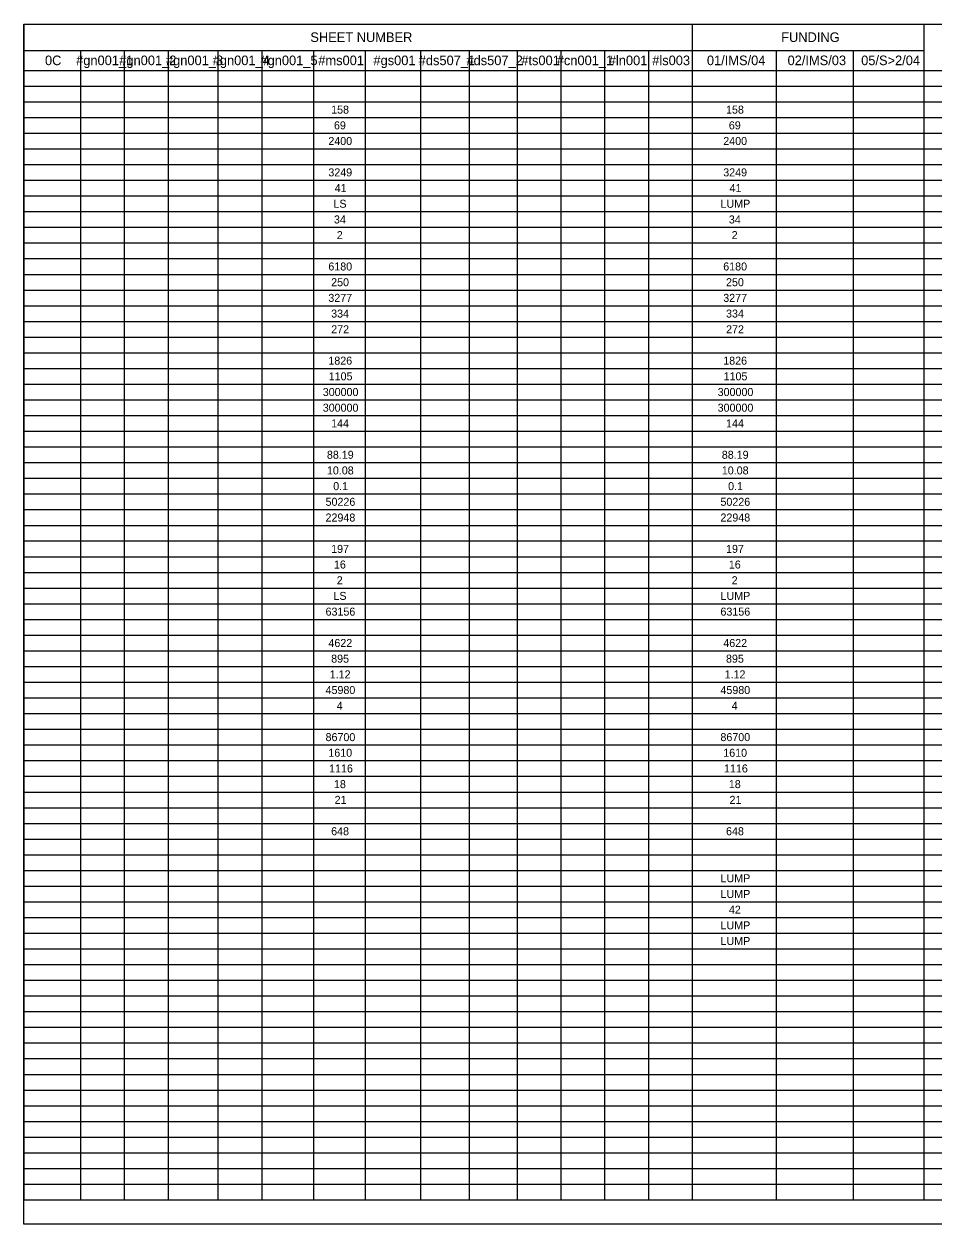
# Model space of a CAD drawing. Extents: x -542 to 295, y -281 to 32.
# Drawn here: x -416.36 to -400.45, y -160.59 to -139.59 of the extents above; entities that cross this region are included whole.
import ezdxf

# ---------------------------------------------------------------- set-up
doc = ezdxf.new("R2010")
doc.units = 0
for name, color, linetype in [('SC_Scratch1', 7, 'Continuous'), ('SH_Data', 7, 'Continuous'), ('SH_Text', 7, 'Continuous')]:
    doc.layers.add(name, color=color, linetype=linetype)

msp = doc.modelspace()

# ---------------------------------------------------------------- linework, layer by layer
at = {"layer": 'SC_Scratch1'}
msp.add_lwpolyline([(-416.359, -139.593), (-385.859, -139.593), (-385.859, -160.593), (-416.359, -160.593)], close=True, dxfattribs=at)
at = {"layer": 'SH_Data'}
for p, q in [((-416.359, -139.593), (-385.859, -139.593)), ((-416.359, -139.593), (-416.359, -160.17)), ((-404.663, -139.593), (-404.663, -160.17)), ((-400.608, -139.593), (-400.608, -160.17)), ((-416.359, -140.054), (-400.608, -140.054)), ((-415.369, -140.054), (-415.369, -160.17)), ((-414.603, -140.054), (-414.603, -160.17)), ((-413.836, -140.054), (-413.836, -160.17)), ((-412.964, -140.054), (-412.964, -160.17)), ((-412.198, -140.054), (-412.198, -160.17)), ((-411.293, -140.054), (-411.293, -160.17)), ((-410.388, -140.054), (-410.388, -160.17)), ((-409.42, -140.054), (-409.42, -160.17)), ((-408.569, -140.054), (-408.569, -160.17)), ((-407.728, -140.054), (-407.728, -160.17)), ((-406.962, -140.054), (-406.962, -160.17)), ((-406.195, -140.054), (-406.195, -160.17)), ((-405.429, -140.054), (-405.429, -160.17)), ((-403.194, -140.054), (-403.194, -160.17)), ((-401.843, -140.054), (-401.843, -160.17)), ((-416.359, -140.405), (-385.859, -140.405)), ((-416.359, -140.68), (-385.859, -140.68)), ((-416.359, -140.954), (-385.859, -140.954)), ((-416.359, -141.229), (-385.859, -141.229)), ((-416.359, -141.503), (-385.859, -141.503)), ((-416.359, -141.778), (-385.859, -141.778)), ((-416.359, -142.052), (-385.859, -142.052)), ((-416.359, -142.327), (-385.859, -142.327)), ((-416.359, -142.601), (-385.859, -142.601)), ((-416.359, -142.876), (-385.859, -142.876)), ((-416.359, -143.15), (-385.859, -143.15)), ((-416.359, -143.425), (-385.859, -143.425)), ((-416.359, -143.699), (-385.859, -143.699)), ((-416.359, -143.974), (-385.859, -143.974)), ((-416.359, -144.248), (-385.859, -144.248)), ((-416.359, -144.523), (-385.859, -144.523)), ((-416.359, -144.797), (-385.859, -144.797)), ((-416.359, -145.072), (-385.859, -145.072)), ((-416.359, -145.346), (-385.859, -145.346)), ((-416.359, -145.621), (-385.859, -145.621)), ((-416.359, -145.895), (-385.859, -145.895)), ((-416.359, -146.17), (-385.859, -146.17)), ((-416.359, -146.444), (-385.859, -146.444)), ((-416.359, -146.719), (-385.859, -146.719)), ((-416.359, -146.993), (-385.859, -146.993)), ((-416.359, -147.268), (-385.859, -147.268)), ((-416.359, -147.542), (-385.859, -147.542)), ((-416.359, -147.817), (-385.859, -147.817)), ((-416.359, -148.091), (-385.859, -148.091)), ((-416.359, -148.366), (-385.859, -148.366)), ((-416.359, -148.64), (-385.859, -148.64)), ((-416.359, -148.915), (-385.859, -148.915)), ((-416.359, -149.189), (-385.859, -149.189)), ((-416.359, -149.464), (-385.859, -149.464)), ((-416.359, -149.738), (-385.859, -149.738)), ((-416.359, -150.013), (-385.859, -150.013)), ((-416.359, -150.287), (-385.859, -150.287)), ((-416.359, -150.562), (-385.859, -150.562)), ((-416.359, -150.836), (-385.859, -150.836)), ((-416.359, -151.111), (-385.859, -151.111)), ((-416.359, -151.385), (-385.859, -151.385)), ((-416.359, -151.66), (-385.859, -151.66)), ((-416.359, -151.935), (-385.859, -151.935)), ((-416.359, -152.209), (-385.859, -152.209)), ((-416.359, -152.484), (-385.859, -152.484)), ((-416.359, -152.758), (-385.859, -152.758)), ((-416.359, -153.033), (-385.859, -153.033)), ((-416.359, -153.307), (-385.859, -153.307)), ((-416.359, -153.582), (-385.859, -153.582)), ((-416.359, -153.856), (-385.859, -153.856)), ((-416.359, -154.131), (-385.859, -154.131)), ((-416.359, -154.405), (-385.859, -154.405)), ((-416.359, -154.68), (-385.859, -154.68)), ((-416.359, -154.68), (-385.859, -154.68)), ((-416.359, -154.954), (-385.859, -154.954)), ((-416.359, -155.229), (-385.859, -155.229)), ((-416.359, -155.503), (-385.859, -155.503)), ((-416.359, -155.778), (-385.859, -155.778)), ((-416.359, -156.052), (-385.859, -156.052)), ((-416.359, -156.327), (-385.859, -156.327)), ((-416.359, -156.601), (-385.859, -156.601)), ((-416.359, -156.876), (-385.859, -156.876)), ((-416.359, -157.15), (-385.859, -157.15)), ((-416.359, -157.425), (-385.859, -157.425)), ((-416.359, -157.699), (-385.859, -157.699)), ((-416.359, -157.974), (-385.859, -157.974)), ((-416.359, -158.248), (-385.859, -158.248)), ((-416.359, -158.523), (-385.859, -158.523)), ((-416.359, -158.797), (-385.859, -158.797)), ((-416.359, -159.072), (-385.859, -159.072)), ((-416.359, -159.346), (-385.859, -159.346)), ((-416.359, -159.621), (-385.859, -159.621)), ((-416.359, -159.895), (-385.859, -159.895)), ((-416.359, -160.17), (-385.859, -160.17))]:
    msp.add_line(p, q, dxfattribs=at)

# ---------------------------------------------------------------- texts
at = {"layer": 'SH_Text'}
for s, height, p in [('SHEET NUMBER', 0.168, (-411.346, -139.907)), ('FUNDING', 0.168, (-403.105, -139.907)), ('0C', 0.168, (-415.991, -140.313)), ('#gn001_1', 0.168, (-415.446, -140.313)), ('#gn001_2', 0.168, (-414.691, -140.313)), ('#gn001_3', 0.168, (-413.873, -140.313)), ('#gn001_4', 0.168, (-413.055, -140.313)), ('#gn001_5', 0.168, (-412.219, -140.313)), ('#ms001', 0.168, (-411.207, -140.313)), ('#gs001', 0.168, (-410.242, -140.313)), ('#ds507_1', 0.168, (-409.449, -140.313)), ('#ds507_2', 0.168, (-408.614, -140.313)), ('#ts001', 0.168, (-407.654, -140.313)), ('#cn001_1', 0.168, (-407.033, -140.313)), ('#ln001', 0.168, (-406.122, -140.313)), ('#ls003', 0.168, (-405.362, -140.313)), ('01/IMS/04', 0.168, (-404.405, -140.313)), ('02/IMS/03', 0.168, (-402.993, -140.313)), ('05/S>2/04', 0.168, (-401.705, -140.313)), ('158', 0.14, (-410.982, -141.161)), ('158', 0.14, (-404.07, -141.161)), ('69', 0.14, (-410.933, -141.436)), ('69', 0.14, (-404.021, -141.436)), ('2400', 0.14, (-411.031, -141.71)), ('2400', 0.14, (-404.119, -141.71)), ('3249', 0.14, (-411.031, -142.259)), ('3249', 0.14, (-404.119, -142.259)), ('41', 0.14, (-410.921, -142.534)), ('41', 0.14, (-404.009, -142.534)), ('LS', 0.14, (-410.942, -142.808)), ('LUMP', 0.14, (-404.166, -142.808)), ('34', 0.14, (-410.933, -143.083)), ('34', 0.14, (-404.021, -143.083)), ('2', 0.14, (-410.884, -143.357)), ('2', 0.14, (-403.972, -143.357)), ('6180', 0.14, (-411.031, -143.906)), ('6180', 0.14, (-404.119, -143.906)), ('250', 0.14, (-410.982, -144.181)), ('250', 0.14, (-404.07, -144.181)), ('3277', 0.14, (-411.031, -144.455)), ('3277', 0.14, (-404.119, -144.455)), ('334', 0.14, (-410.982, -144.73)), ('334', 0.14, (-404.07, -144.73)), ('272', 0.14, (-410.981, -145.005)), ('272', 0.14, (-404.069, -145.005)), ('1826', 0.14, (-411.031, -145.554)), ('1826', 0.14, (-404.119, -145.554)), ('1105', 0.14, (-411.025, -145.828)), ('1105', 0.14, (-404.113, -145.828)), ('300000', 0.14, (-411.129, -146.103)), ('300000', 0.14, (-404.217, -146.103)), ('300000', 0.14, (-411.129, -146.377)), ('300000', 0.14, (-404.217, -146.377)), ('144', 0.14, (-410.982, -146.652)), ('144', 0.14, (-404.07, -146.652)), ('88.19', 0.14, (-411.056, -147.201)), ('88.19', 0.14, (-404.144, -147.201)), ('10.08', 0.14, (-411.056, -147.475)), ('10.08', 0.14, (-404.144, -147.475)), ('0.1', 0.14, (-410.946, -147.75)), ('0.1', 0.14, (-404.034, -147.75)), ('50226', 0.14, (-411.08, -148.024)), ('50226', 0.14, (-404.168, -148.024)), ('22948', 0.14, (-411.08, -148.299)), ('22948', 0.14, (-404.168, -148.299)), ('197', 0.14, (-410.982, -148.848)), ('197', 0.14, (-404.07, -148.848)), ('16', 0.14, (-410.933, -149.122)), ('16', 0.14, (-404.021, -149.122)), ('2', 0.14, (-410.884, -149.397)), ('2', 0.14, (-403.972, -149.397)), ('LS', 0.14, (-410.942, -149.671)), ('LUMP', 0.14, (-404.166, -149.671)), ('63156', 0.14, (-411.08, -149.946)), ('63156', 0.14, (-404.168, -149.946)), ('4622', 0.14, (-411.03, -150.495)), ('4622', 0.14, (-404.118, -150.495)), ('895', 0.14, (-410.982, -150.769)), ('895', 0.14, (-404.071, -150.769)), ('1.12', 0.14, (-411.007, -151.044)), ('1.12', 0.14, (-404.095, -151.044)), ('45980', 0.14, (-411.08, -151.318)), ('45980', 0.14, (-404.168, -151.318)), ('4', 0.14, (-410.884, -151.593)), ('4', 0.14, (-403.972, -151.593)), ('86700', 0.14, (-411.08, -152.142)), ('86700', 0.14, (-404.168, -152.142)), ('1610', 0.14, (-411.031, -152.416)), ('1610', 0.14, (-404.119, -152.416)), ('1116', 0.14, (-411.018, -152.691)), ('1116', 0.14, (-404.106, -152.691)), ('18', 0.14, (-410.933, -152.965)), ('18', 0.14, (-404.021, -152.965)), ('21', 0.14, (-410.921, -153.24)), ('21', 0.14, (-404.009, -153.24)), ('648', 0.14, (-410.982, -153.789)), ('648', 0.14, (-404.07, -153.789)), ('LUMP', 0.14, (-404.166, -154.612)), ('LUMP', 0.14, (-404.166, -154.887)), ('42', 0.14, (-404.02, -155.161)), ('LUMP', 0.14, (-404.166, -155.436)), ('LUMP', 0.14, (-404.166, -155.71))]:
    msp.add_text(s, height=height, dxfattribs=at).set_placement(p)

doc.saveas('drawing.dxf')
